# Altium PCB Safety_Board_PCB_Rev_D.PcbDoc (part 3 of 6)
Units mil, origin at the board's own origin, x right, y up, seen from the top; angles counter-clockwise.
Board outline 11000 x 4400 mil, 6 copper layers (L1-TOP, L2-Plane, L3-Signal, L4-Signal, L5-Plane, L6-BOT); 712 components, 540 nets, 2214 pads, 875 vias.
Unrouted connection lines stored in the file: 3.
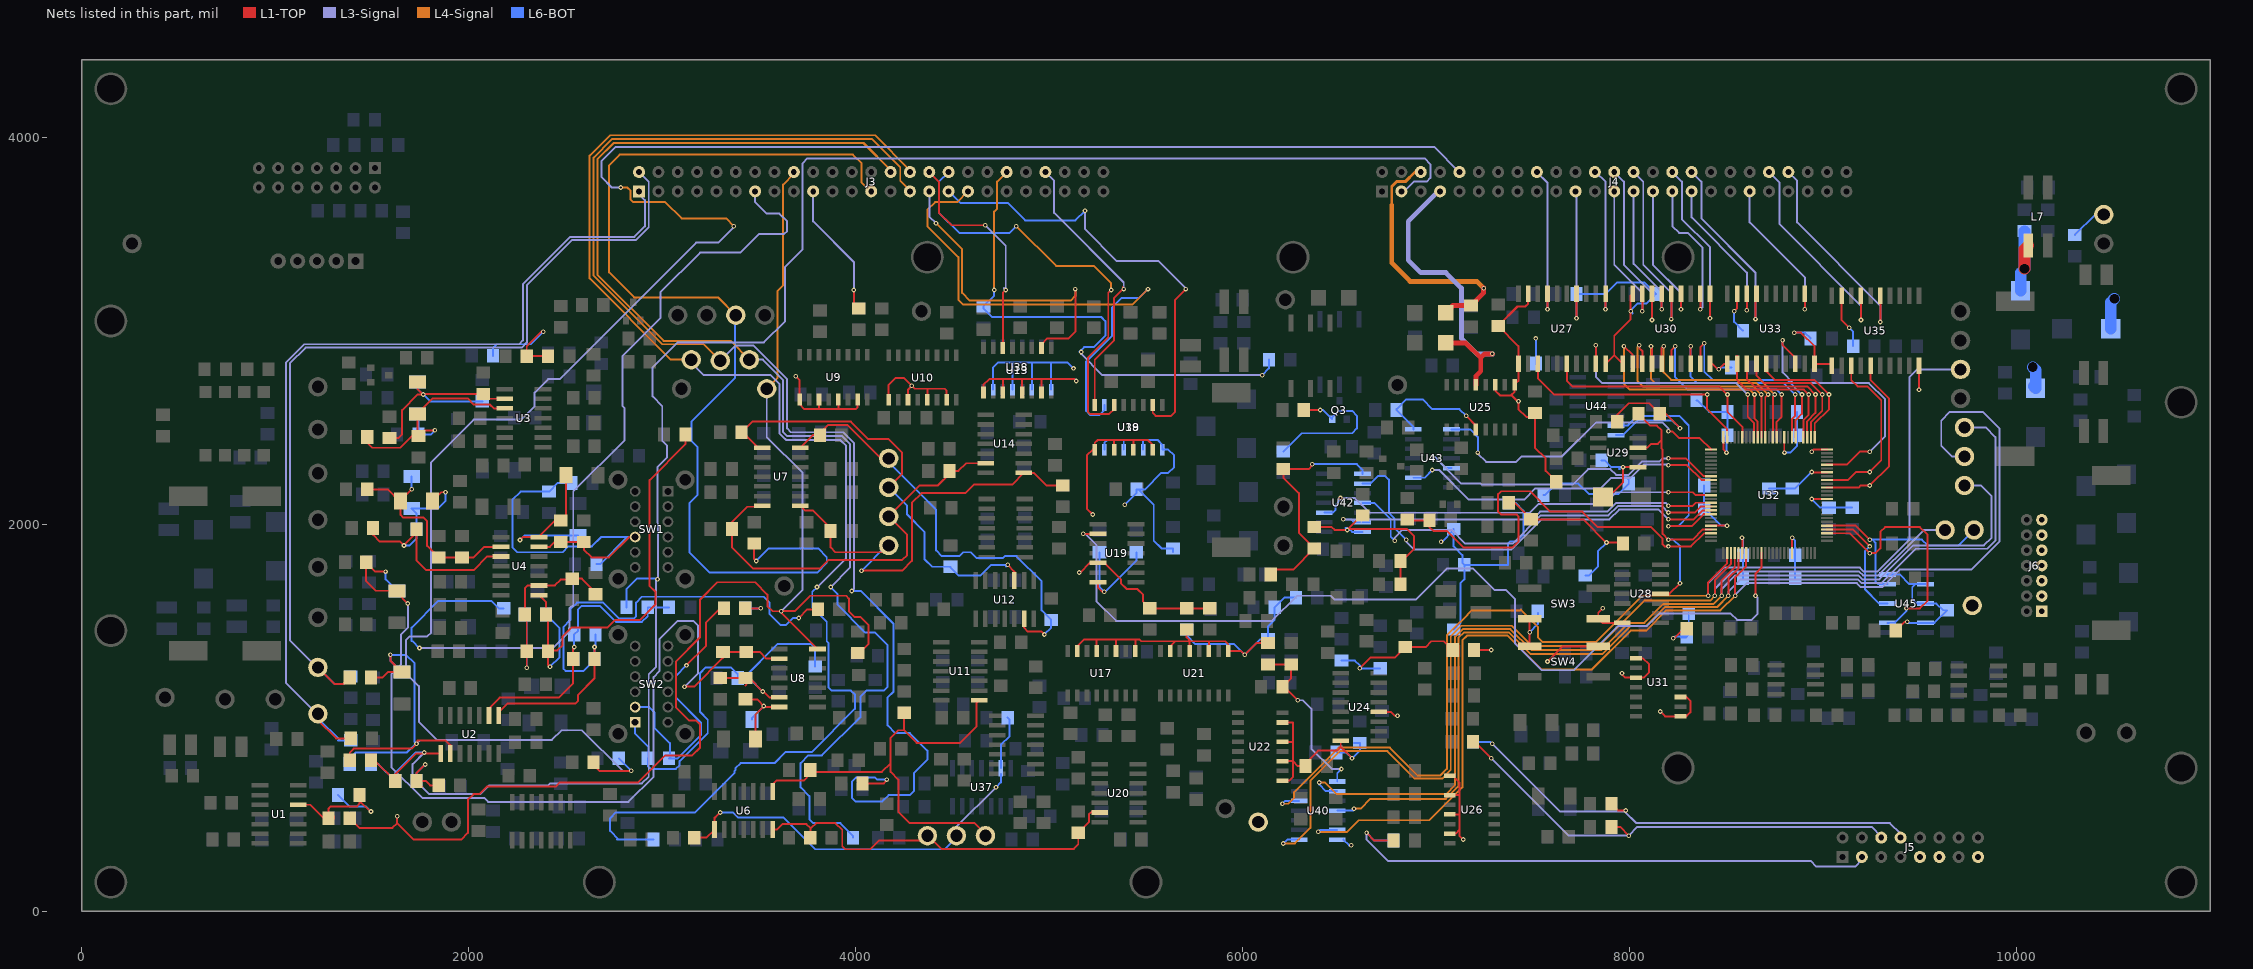
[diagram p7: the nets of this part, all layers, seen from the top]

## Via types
v1: diameter 24, hole 12, L1-TOP to L6-BOT, 720 vias
v2: diameter 50, hole 28, L1-TOP to L6-BOT, 138 vias
v3: diameter 28, hole 50, L1-TOP to L6-BOT, 17 vias

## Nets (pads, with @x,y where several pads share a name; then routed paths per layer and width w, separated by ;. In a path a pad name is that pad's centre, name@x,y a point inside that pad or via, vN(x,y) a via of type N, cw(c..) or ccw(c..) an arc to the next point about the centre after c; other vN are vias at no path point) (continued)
DEC_OVERSPEED_N: TP47.1 U32.55 U45.6 | length 1125.4
  L1-TOP w10: U32.55@9019.21,1992.52 9167.48,1992.52 v1(9240,1920)
  L6-BOT w10: v1(9240,1920) 9510,1920 9540,1890 9700,1890 TP47.1@9780,1970 ; 9255,1920 9270,1905 9270,1705 9285,1690 U45.6@9331.57,1690
DEC_STOP_N_LATCH: U32.77 U33.4 | length 685.3
  L1-TOP w10: U33.4@8655,2828.9 8655,2770 8696,2729 8936,2729 v1(8995,2670) 8995,2585 8936.54,2526.54 U32.77@8936.54,2449.21
DEC_STOP_NORTH_BUF_N: U32.9 U43.2 | length 1727
  L1-TOP w10: v1(8200,2305) 8295,2305 8371.26,2228.74 U32.9@8420.79,2228.74
  L3-Signal w10: v1(6980,2280) 7015,2280 7168,2127 7454.67,2127 7512.67,2185 7850,2185 7903,2238 8003,2238 8073,2308 8197,2308 v1(8200,2305)
  L6-BOT w10: U43.2@6881.57,2240 6940,2240 v1(6980,2280)
DEC_STOP_S_LATCH: U32.76 U33.5 | length 665
  L1-TOP w10: U33.5@8705,2828.9 8705,2790 8749,2746 8954,2746 v1(9030,2670) 9030,2595 8956.22,2521.22 U32.76@8956.22,2449.21
DEC_STOP_SOUTH_BUF_N: U32.16 U42.4 | length 2102.8
  L1-TOP w10: v1(8200,2060) 8335,2060 8365.94,2090.94 U32.16@8420.79,2090.94
  L3-Signal w10: v1(6785,1915) 6785,1930 6825,1970 7080,1970 7150,1900 7395.96,1900 7540.96,2045 7890,2045 7938,2093 8167,2093 v1(8200,2060)
  L6-BOT w10: U42.4@6618.43,2110 6680,2110 6765,2025 6765,1935 v1(6785,1915)
DGND: C25.1 C26.1 C27.1 C28.1 C29.1 C30.1 C31.1 C32.1 C33.1 C34.1 C35.1 C36.1 C37.1 C38.2 C39.1 C40.1 C42.1 C104.1 C105.1 C106.1 C108.1 C109.1 C114.1 C115.1 C116.1 C117.1 C118.1 C119.1 C120.1 C121.1 C122.1 C123.1 C124.1 C125.1 C126.1 C127.1 C128.1 C129.1 C130.1 C131.1 C132.1 C133.1 C134.1 C135.1 C136.1 C137.1 C138.1 C139.1 C140.1 C141.1 C142.1 C143.1 C144.1 C145.1 C146.1 C147.1 C148.1 C149.1 C150.1 C151.1 C152.1 C154.1 C155.1 C156.1 C157.2 C159.2 C161.2 J5.15 J6.1 J6.3 J6.5 J6.7 J6.9 J6.11 J6.13 L7.3 Q3.2 R128.2 R153.1 R161.1 R169.1 R374.1 R383.2 R387.1 SW3.1 SW3.3 SW4.1 SW4.3 TP34.1 TP48.1 TP50.1 U9.9 U9.11 U9.13 U9.15 U10.9 U10.11 U10.13 U10.15 U13.9 U13.11 U13.13 U13.15 U17.9 U17.11 U17.13 U17.15 U18.9 U18.11 U18.13 U18.15 U19.7 U21.9 U21.11 U21.13 U21.15 U22.9 U22.11 U22.13 U22.15 U24.8 U24.12 U25.4 U25.9 U25.11 U26.9 U26.11 U26.13 U26.15 U27.1 U27.10 U27.19 U28.7 U29.1 U30.1 U30.10 U30.19 U31.2 U31.4 U31.9 U31.11 U32.21 U32.31 U32.44 U32.62 U32.69 U32.75 U32.84 U32.100 U33.1 U33.10 U33.19 U35.1 U35.10 U35.19 U38.9 U38.11 U38.13 U38.15 U39.9 U39.11 U39.13 U39.15 U40.7 U42.7 U43.7 U44.7 U45.7 U45.9 U45.11 U45.13 | length 27059.8
  L1-TOP w10: v1(3690,2765) 3710,2745 3710,2620 3735,2595 4000,2595 4010,2605 U9.15@4010,2644.84 ; 3810,2595 U9.11@3810,2644.84 ; 3910,2595 U9.13@3910,2644.84 ; U10.9@4170,2642.84 4170,2720 4205,2755 4250,2755 4305,2700 4460,2700 4470,2690 U10.15@4470,2642.84 ; U10.11@4270,2642.84 4270,2695 v1(4290,2715) ; U10.13@4370,2642.84 4370,2700 ; U13.9@4660,2679.84 4660,2720 4690,2750 5130,2750 v1(5140,2740) ; U13.11@4760,2679.84 4760,2750 ; U13.13@4860,2679.84 4860,2750 ; U13.15@4960,2679.84 4960,2750 ; U17.15@5145,1345.16 5145,1370 5180,1405 5465,1405 5475,1395 5910,1395 5925,1380 U21.9@5925,1345.16 5989.84,1345.16 v1(6010,1325) 6070.12,1385.12 C26.1@6130,1385.12 ; v1(5225,2050) 5195,2080 5195,2355 5224.84,2384.84 U18.9@5235,2384.84 5235,2420 5250,2435 5510,2435 5535,2410 U18.15@5535,2384.84 ; U17.13@5245,1345.16 5245,1405 ; U19.7@5251.57,1700 5251.57,1673.43 5275,1650 v1(5285,1650) ; U18.11@5335,2384.84 5335,2435 ; U17.11@5345,1345.16 5345,1405 ; U18.13@5435,2384.84 5435,2435 ; 5440,1405 5445,1400 U17.9@5445,1345.16 ; U21.15@5625,1345.16 5625,1370 5650,1395 ; C25.1@5710,1454.88 5710,1415 5730,1395 ; U21.13@5725,1345.16 5725,1395 ; U21.11@5825,1345.16 5825,1395 ; C26.1@6095.12,1400.12 C26.1@6135,1400.12 ; U22.9@6205.16,675 6240,675 6260,695 6260,975 U22.15@6205.16,975 ; U22.11@6205.16,775 6260,775 6285,750 C28.1@6324.88,750 6324.88,764.88 6390,830 6488.15,830 6506.57,848.43 ; U22.13@6205.16,875 6260,875 ; R128.2@6305,2600.12 R128.2@6315.12,2590 v1(6400,2590) ; C27.1@6370,1985.12 6459.88,1985.12 6475,1970 v1(6540,1970) 6614.88,2044.88 C29.1@6620,2044.88 ; U24.8@6506.57,880 6506.57,848.43 ; v1@6545,1975 6850,1975 6885,1940 6885,1870 6825,1810 C30.1@6815.12,1810 C31.1@6815.12,1690 ; v1(6565,790) 6506.57,848.43 ; v1(6605,1255) 6660,1310 6785.12,1310 C32.1@6840,1364.88 6944.88,1364.88 6975,1395 7039.88,1395 R153.1@7084.88,1350 ; U24.12@6703.43,1030 6765,1030 6785,1010 v1(6800,1010) ; v1(7025,1910) v1@7030,1915 ; U26.15@7069.84,400 7100,400 7120,420 ; U26.13@7069.84,500 7120,500 ; U26.11@7069.84,600 7120,600 ; U26.9@7069.84,700 7085,700 7120,665 7120,390 v1(7140,370) ; v1(7155,2560) 7205,2510 U25.4@7205,2489.84 ; U25.11@7305,2720.16 7305,2690 7330,2665 7390,2665 7420,2635 v1(7425,2635) 7425,2595 7465.12,2554.88 R161.1@7510,2554.88 ; C33.1@7320,3024.88 7425,2919.88 7425,2740.16 U25.9@7405,2720.16 7405,2685 7385,2665 ; C33.1@7320,3025 7420,3125 7460,3125 7475,3140 U27.19@7475,3191.1 ; C34.1@7375.12,2110 7405.12,2110 C35.1@7490,2025.12 7759.88,2025.12 v1@7885,1900 ; SW4.1@7482.83,1368.74 SW3.3@7482.83,1511.26 ; R161.1@7510,2574.88 7510,2395 7565,2340 7565,2274.88 C36.1@7619.88,2220 ; v1(7575,1290) 7653.74,1368.74 SW4.3@7837.17,1368.74 ; v1(7860,1565) 7837.17,1542.16 SW3.1@7837.17,1511.26 7858.43,1490 U28.7@7961.57,1490 ; C38.2@7861.57,2140 7890,2140 7964.96,2214.96 v1(7964.96,2295.04) U29.1@8042.32,2295.04 ; U27.10@7876.1,2828.9 U27.10@7875,2828.9 7920,2873.9 ; v1(7880,1905) 7959.88,1905 C39.1@7964.88,1900 ; C37.1@7935.12,2530 7935.12,2565.12 7995,2625 8100.12,2625 R169.1@8155.12,2570 8185,2570 v1(8260,2495) ; v1(7960,1230) 7960,1225 7978.08,1206.92 8071.92,1206.92 8100,1235 8100,1275 8068.08,1306.92 U31.2@8032.81,1306.92 ; U30.1@7963.9,2828.9 U30.1@7965,2828.9 7920,2873.9 ; U30.19@8015,3191.1 8005,3181.1 8005,3060 7920,2975 7920,2873.9 ; v1(8157.96,1031.92) 8182.96,1006.92 8292.96,1006.92 8312.96,1026.92 8312.96,1086.92 8292.96,1106.92 U31.11@8263.12,1106.92 ; v1(8225,1410) 8230,1410 8280,1460 C40.1@8294.88,1460 ; U30.10@8415,2828.9 8426.1,2828.9 8455,2800 v1(8460,2800) 8488.9,2828.9 U33.1@8505,2828.9 ; U32.21@8420.79,1992.52 v1(8502.48,1992.52) ; U32.100@8483.78,2449.21 8483.78,2386.22 v1(8500,2370) ; v1(8540,3100) 8555,3115 U33.19@8555,3191.1 ; v1(8580,1930) 8582.2,1927.8 U32.31@8582.2,1850.79 ; U32.84@8798.74,2449.21 8798.74,2366.26 8800,2365 v1(8800,2370) ; U32.44@8838.11,1850.79 8838.11,1933.11 8840,1935 v1(8840,1930) ; v1(8850,2990) 8885,2990 8955,2920 U33.10@8955,2828.9 9035,2828.9 U35.1@9045,2818.9 ; v1(8940,2130) 8940.32,2130.32 U32.62@9019.21,2130.32 ; v1(8940,2270) 8941.89,2268.11 U32.69@9019.21,2268.11 ; v1(8940,2375) 8951.22,2386.22 U32.75@9019.21,2386.22 ; U35.19@9095,3181.1 9095,3055 v1(9135,3015) ; C42.1@9375.12,1450 9420.12,1495 v1(9435,1495) ; v1(9495,2695) U35.10@9495,2818.9
  L1-TOP w60: v3(10040,3320) 10040,3420 L7.3@10060,3440
  L6-BOT w10: U38.15@4710,2694.84 4710,2810 4735,2835 5095,2835 v1(5125,2805) ; U38.13@4810,2694.84 4810,2835 ; U38.11@4910,2694.84 4910,2835 ; U38.9@5010,2694.84 5010,2835 ; C105.1@5260,1854.88 5260,1675 v1(5285,1650) ; U39.15@5285,2384.84 5285,2420 5300,2435 5560,2435 5585,2410 U39.9@5585,2384.84 5615.16,2384.84 5645,2355 5645,2295 5615,2265 5580,2265 5495,2180 C104.1@5450.24,2180 5450.24,2160.24 v1(5390,2100) ; v1@5288.34,1650 5450,1811.66 C106.1@5450,1854.88 ; U39.13@5385,2384.84 5385,2435 ; C104.1@5460,2180 5540,2100 5540,1915 5580.12,1874.88 C108.1@5640,1874.88 C108.1@5640,1855 ; U39.11@5485,2384.84 5485,2435 ; C109.1@5710,1454.88 5710,1425 5755,1380 5955,1380 v1(6010,1325) 6090.12,1405.12 C115.1@6130,1405.12 6130,1470 6165.12,1505.12 C114.1@6165.12,1570 6215.12,1620 C117.1@6274.88,1620 ; C116.1@6210,2375.12 6304.88,2470 6565,2470 6590,2495 6590,2560 6565,2585 6495,2585 6462.6,2552.6 Q3.2@6462.6,2542.76 6415.35,2590 v1(6400,2590) ; C118.1@6485.12,820 6535,820 v1(6565,790) 6605,830 C120.1@6605,869.88 C120.1@6574.88,869.88 ; C119.1@6510,1295.12 6579.88,1295.12 6605,1270 v1(6605,1255) 6709.88,1255 C122.1@6710,1255.12 ; U40.7@6520,370 6550,340 v1(6560,340) ; 6530,1980 v1@6540,1980 ; v1(6540,1970) 6555,1970 6565,1960 U42.7@6618.43,1960 ; U43.7@6881.57,2490 6881.57,2503.54 C121.1@6795.12,2590 6795.12,2595.12 6845,2645 6930,2645 6980,2595 7120,2595 v1(7155,2560) ; v1(7025,1910) 7025,1905 C123.1@7090,1970 ; C125.1@7090,1455.12 7125,1490.12 7125,1695 7145.12,1715.12 C124.1@7145.12,1790 ; C123.1@7090,1974.88 7090,1885 7135.12,1839.88 7135.12,1800 C124.1@7145.12,1790 ; C126.1@7375.12,2110 7410,2110 7450,2070 7450,1945 7415,1910 7380,1910 7370,1900 7370,1790 C124.1@7145.12,1790 ; v1(7482.83,1442.16) 7525.12,1484.45 C127.1@7525.12,1540 ; C128.1@7514.88,2830 7514.88,2959.88 v1(7515,2960) ; C130.1@7554.88,2150 7560,2150 7620,2210 7735,2210 7790,2155 7939.88,2155 C133.1@7994.88,2210 7994.88,2230.12 7964.96,2260.04 v1(7964.96,2295.04) 7904.96,2295.04 7870,2330 C132.1@7855.12,2330 ; C129.1@7725.12,3190 7875,3190 7935,3250 8075.12,3250 C134.1@8135.12,3190 8085.12,3140 8040,3140 8005,3105 v1(8005,3100) ; C131.1@7770,1735.12 7790.12,1735.12 7835,1780 7835,1860 v1(7880,1905) ; U44.7@7928.43,2460 7965,2460 8040,2535 8220,2535 v1(8260,2495) ; 7945,2285 7950,2285 ; v1@8000,3100 v1(8005,3100) ; 8015.12,3089.88 v1(8005,3100) ; v1(8225,1410) 8235,1420 C141.1@8294.88,1420 ; C141.1@8265,1415 8289.88,1415 8305.12,1430.24 C136.1@8305.12,1540 ; C135.1@8345.12,2640 8350,2640 8410,2580 C145.1@8504.88,2580 C137.1@8504.88,2460 8500,2455.12 v1(8500,2370) ; C142.1@8384.88,2200 C138.1@8384.88,2080 8472.36,1992.52 v1(8502.48,1992.52) ; v1(8460,2800) 8470,2810 C144.1@8524.88,2810 ; v1(8540,3100) 8540,3045.12 C143.1@8585.12,3000 ; v1(8580,1930) 8585.12,1924.88 C140.1@8585.12,1720 ; C146.1@8720,2185.12 C149.1@8840,2185.12 8855.12,2185.12 v1(8940,2270) ; v1(8800,2370) 8830,2370 8865.12,2405.12 C147.1@8865.12,2580 ; v1(8840,1930) 8855.12,1914.88 C151.1@8855.12,1720 ; v1(8850,2990) 8904.88,2990 C152.1@8934.88,2960 ; v1(8940,2130) 8984.88,2085.12 C155.1@9150,2085.12 ; v1(9135,3015) 9154.88,2995.12 R374.1@9154.88,2920 ; U45.7@9331.57,1740 9395,1740 9445,1690 U45.9@9528.43,1690 ; v1(9435,1495) 9440,1490 9574.88,1490 C156.1@9640,1555.12 9619.88,1555.12 9585,1590 9485,1590 9460,1615 9460,1675 9475,1690 ; R387.1@10300,3495.12 10300.12,3495.12 10405,3600 TP50.1@10450,3600
  L6-BOT w60: C157.2@10020,3205.98 10020,3300 ; v3(10040,3320) R383.2@10040,3514.88 ; v3(10082.96,2811.92) 10097.96,2796.92 C159.2@10097.96,2702.9 C159.2@10087.96,2712.9 ; C161.2@10485.98,3010 10485.98,3145.98 v3(10505,3165)
"DOME1 CURRENT": J3.28 R252.1 TP22.1 | length 6741.3
  L4-Signal w10: TP22.1@3450,2850 3353,2947 3007.04,2947 2665,3289.04 2665,3885 2750,3970 4040,3970 4180,3830 J3.28@4180,3820
  L3-Signal w10: TP22.1@3450,2850 3520,2850 3625,2745 3625,2475 3645,2455 3930,2455 3970,2415 3970,1775 v1(3870,1675)
  L6-BOT w10: v1(3870,1675) 3905,1640 3905,1585 4050,1440 4100,1440 4165,1375 4165,1160 4145,1140 4055,1140 4025,1110 4025,1005 3824.62,804.62 3754.62,804.62 3715,765 3715,640 3760,595 3760,475 3780,455 3920,455 3985.12,389.88 R252.1@3985.12,380
"DOME1 OC LATCH": J4.24 U27.11 | length 816.8
  L1-TOP w10: v1(7875,3110) U27.11@7875,3191.1
  L3-Signal w10: J4.24@7820,3820 7825,3820 7875,3770 v1(7875,3110)
DOME1_OVERCURRENT_LATCH: U27.9 U32.92 | length 1315.9
  L1-TOP w10: U27.9@7825,2828.9 v1(7825,2925) ; v1(8610,2670) 8610,2555 8641.26,2523.74 U32.92@8641.26,2449.21
  L3-Signal w10: v1(7825,2925) 7825,2762 7858,2729 8551,2729 v1(8610,2670)
DOME1_OVERCURRENT_N: TP44.1 U32.30 U40.4 | length 5510
  L1-TOP w10: v1(8510,1630) 8510,1720 8562.52,1772.52 U32.30@8562.52,1850.79
  L4-Signal w10: v1(6575,530) 6610,530 6660,580 7049.92,580 7115,645.08 7115,1411.92 7144.08,1441 7375.92,1441 7486.92,1330 7860,1330 8003,1473 8083,1473 8181,1571 8451,1571 v1(8510,1630)
  L3-Signal w10: v1(8510,1630) 8510,1650 8575,1715 9177.88,1715 9197.88,1695 9300,1695 9478,1873 9848,1873 9890,1915 9890,2450 9840,2500 TP44.1@9730,2500
  L6-BOT w10: U40.4@6488.43,520 6570,520 6575,525 v1(6575,530)
"DOME2 CURRENT": J3.29 R76.1 TP19.1 | length 7217.2
  L1-TOP w10: R76.1@4035.12,660 4145,660 4165,680 v1(4160,680)
  L4-Signal w10: TP19.1@3300,2845 3215,2930 3000,2930 2645,3285 2645,3895 2740,3990 4085,3990 4230,3845 4230,3775 4280,3725 J3.29@4280,3720
  L3-Signal w10: TP19.1@3300,2845 3378,2923 3472,2923 3645,2750 3645,2495 3665,2475 3935,2475 3990,2420 3990,1665 v1(3980,1655)
  L6-BOT w10: v1(3980,1655) 4025,1655 4195,1485 4195,1135 4165,1105 4165,960 4205,920 4280,920 4370,830 4370,783.34 4300,713.34 4300,620 4280,600 4170,600 4137,567 3998,567 3980,585 3980,670 4000,690 4100,690 4110,680 v1(4160,680)
"DOME2 OC LATCH": J4.25 U30.18 | length 771.2
  L1-TOP w10: v1(8065,3100) U30.18@8065,3191.1
  L3-Signal w10: J4.25@7920,3720 7920,3340 8065,3195 v1(8065,3100)
DOME2_OVERCURRENT_LATCH: U30.2 U32.91 | length 1229.9
  L1-TOP w10: v1(7970,2920) 8015,2875 U30.2@8015,2828.9 ; v1(8645,2670) 8645,2545 8660.94,2529.06 U32.91@8660.94,2449.21
  L4-Signal w10: v1(7970,2920) 7970,2725 8000,2695 8620,2695 v1(8645,2670)
DOME2_OVERCURRENT_N: TP45.1 U32.32 U40.6 | length 6308.7
  L1-TOP w10: v1(8545,1630) 8545,1725 8601.89,1781.89 U32.32@8601.89,1850.79
  L4-Signal w10: v1(6390,410) 6540,410 6600,470 6963.96,470 7113,619.04 7114.04,619.04 7135,640 7135,1400 7159,1424 7368.88,1424 7542.88,1250 7805,1250 8005,1450 8085,1450 8189,1554 8469,1554 v1(8545,1630)
  L3-Signal w10: v1(8545,1630) 8545,1635 8605,1695 9173.83,1695 9193.83,1675 9305,1675 9395,1765 9765,1765 9910,1910 9910,2495 9825,2580 9655,2580 9610,2535 9610,2405 9665,2350 TP45.1@9730,2350
  L6-BOT w10: v1(6390,410) 6400,420 U40.6@6488.43,420
"DOME3 CURRENT": J3.30 R239.1 TP18.1 | length 7701
  L4-Signal w10: TP18.1@3150,2850 3045,2850 2625,3270 2625,3905 2730,4010 4100,4010 4280,3830 J3.30@4280,3820
  L3-Signal w10: TP18.1@3180,2850 TP18.1@3150,2850 3150,2835 3215,2770 3560,2770 3605,2725 3605,2470 3635,2440 3635.96,2440 3640.96,2435 3920,2435 3950,2405 3950,1825 v1(3800,1675)
  L6-BOT w10: 2765,370 R239.1@2954.88,370 ; 2775,370 2730,415 2730,480 2760,510 3170,510 3373.13,713.13 3373.13,723.53 3377.77,728.16 3377.77,737.77 3405,765 3580,765 3636.62,821.62 3771.62,821.62 3995,1045 3995,1120 3975,1140 3875,1140 3860,1155 3860,1385 3850,1395 3850,1495 3775,1570 3775,1650 v1(3800,1675)
"DOME3 OC LATCH": J4.26 U30.17 | length 981.9
  L1-TOP w10: v1(8115,3055) U30.17@8115,3191.1
  L3-Signal w10: J4.26@7920,3820 7970,3770 7970,3340 8115,3195 v1(8115,3055)
DOME3_OVERCURRENT_LATCH: U30.3 U32.90 | length 1181.5
  L1-TOP w10: v1(8050,2925) 8050,2910 8065,2895 U30.3@8065,2828.9 ; v1(8680,2670) 8680.63,2669.37 U32.90@8680.63,2449.21
  L4-Signal w10: v1(8050,2925) 8040,2915 8040,2740 8068,2712 8638,2712 v1(8680,2670)
DOME3_OVERCURRENT_N: TP46.1 U32.29 U40.2 | length 5369
  L1-TOP w10: v1(8475,1630) 8475,1710 8542.83,1777.83 U32.29@8542.83,1850.79
  L4-Signal w10: v1(6395,665) 6425,665 6485,605 7050.88,605 7098,652.12 7098,1418.96 7137.04,1458 7382.96,1458 7490.96,1350 7855,1350 7995,1490 8075.96,1490 8173.96,1588 8433,1588 v1(8475,1630)
  L3-Signal w10: v1(8475,1630) 8475,1665 8545,1735 9181.92,1735 9201.92,1715 9290,1715 9465,1890 9830,1890 9870,1930 9870,2145 9815,2200 TP46.1@9730,2200
  L6-BOT w10: v1(6395,665) 6395,655 6430,620 U40.2@6488.43,620
"DOME AMP": D12.K J4.6 R151.1 | length 1366.9
  L1-TOP w25: D12.K@7050,3093.5 7086.62,3130.12 R151.1@7180,3130.12 7245,3195.12 v1(7245,3220)
  L4-Signal w15: 6770,3650 6770,3745 6795,3770 6840,3770 6890,3820 J4.6@6920,3820
  L4-Signal w25: 6770,3650 6770,3350 6865,3255 7210,3255 v1(7245,3220)
"DOME AMP ENABLE & THERM STAT LATCH": J4.42 U35.17 | length 1087.9
  L1-TOP w10: v1(9195,3055) U35.17@9195,3181.1
  L3-Signal w10: J4.42@8720,3820 8775,3765 8775,3550 9195,3130 v1(9195,3055)
"DOME AMP RET": D12.A J4.7 U25.13 | length 1647.6
  L1-TOP w25: D12.A@7050,2936.5 7153.5,2936.5 7230,2860 ; U25.13@7205,2720.16 7205,2765 7230,2790 7230,2860 ; v1(7290,2880) 7250,2880 7230,2860
  L3-Signal w25: J4.7@7020,3720 7010,3720 6855,3565 6855,3365 6920,3300 7050,3300 7130,3220 7130,2960 7210,2880 v1(7290,2880)
DOME_AMP_ENABLE_&_THERM_STAT: U32.8 U43.12 | length 1738.7
  L1-TOP w10: v1(8200,2340) 8290,2340 8381.57,2248.43 U32.8@8420.79,2248.43
  L3-Signal w10: v1(6980,2345) 6995,2345 7130,2210 7230,2210 7235,2205 7705,2205 7785,2285 7900,2285 7930,2255 7995,2255 8065,2325 8155,2325 8170,2340 v1(8200,2340)
  L6-BOT w10: v1(6980,2345) 6995,2345 7050,2290 U43.12@7078.43,2290
DOME_AMP_ENABLE_&_THERM_STAT_LATCH: U32.67 U35.3 | length 905.1
  L1-TOP w10: U32.67@9019.21,2228.74 9128.74,2228.74 9170,2270 v1(9240,2270) 9300,2330 9300,2640 9228,2712 9178,2712 9145,2745 U35.3@9145,2818.9
DOME_AMP_ENABLE_N: R146.1 R150.2 U32.23 | length 2274.1
  L1-TOP w10: R146.1@6850,2024.88 6854.88,2020 R150.2@6964.88,2020 6964.88,1985.12 6985,1965 7055,1965 7140,1880 7395,1880 7425,1910 7425,2040 7415,2050 7335,2050 7320,2065 7320,2155 7335,2170 7485,2170 7590,2065 7755,2065 7835,1985 8110,1985 8170,1925 8170,1895 8180,1885 8315.96,1885 8384.11,1953.15 U32.23@8420.79,1953.15
  other v1: 8200,1885
"EAST CURRENT": J3.25 R58.1 TP20.1 | length 5424
  L1-TOP w10: R58.1@3475,1899.88 3475,1820 v1(3485,1810)
  L4-Signal w10: TP20.1@3380,3080 3288,3172 2854.17,3172 2725,3301.17 2725,3855 2780,3910 3985,3910 4030,3865 4030,3765 4075,3720 J3.25@4080,3720
  L6-BOT w10: 3375,3030 3375,2755 3150,2530 3150,2430 3183,2397 3183,2152.04 3140,2109.04 3140,1855 3245,1750 3800,1750 3850,1800 3850,1830 3805,1875 3550,1875 v1(3485,1810)
"EAST DRIVE+": C57.2 J3.1 R16.1 TP12.1 | length 4886.7
  L1-TOP w10: TP12.1@1220,1020 1220,987.76 1314.65,893.11 R16.1@1389.53,893.11
  L3-Signal w10: TP12.1@1220,1020 1215,1020 1055,1180 1055,2835 1150,2930 2260,2930 2280,2950 2280,3240 2525,3485 2855.96,3485 2910,3539.04 2910,3675 2880,3705 J3.1@2880,3720
  L6-BOT w10: TP12.1@1220,1020 1220,997.99 1335,882.99 ; 1324.76,882.99 C57.2@1389.65,882.99
"EAST DRIVE-": C54.2 J3.2 R15.1 TP11.1 | length 4693.8
  L1-TOP w10: TP11.1@1220,1260 1305,1175 1351.42,1175 R15.1@1384.53,1208.11
  L3-Signal w10: TP11.1@1220,1260 1215,1260 1075,1400 1075,2830.96 1157.04,2913 2273,2913 2300,2940 2300,3235.96 2532.04,3468 2863,3468 2930,3535 2930,3770 J3.2@2880,3820
  L6-BOT w10: TP11.1@1220,1260 1305,1175 1351.42,1175 C54.2@1389.65,1213.23
"EAST OC LATCH": J4.21 U27.14 | length 783.2
  L1-TOP w10: v1(7725,3065) U27.14@7725,3191.1
  L3-Signal w10: J4.21@7720,3720 7725,3715 v1(7725,3065)
"EAST TACH OUT": C4.1 C8.1 J4.3 R207.1 R212.1 R236.1 U2.1 | length 9949.5
  L1-TOP w10: C4.1@1495.12,780 1512.64,780 C8.1@1619.53,673.11 1619.53,707.99 1726.22,814.69 1764.69,814.69 v1(1770,820) 1775.31,814.69 U2.1@1854.65,814.69
  L3-Signal w10: v1(1770,820) 1710,760 1710,690 1795,605 2060,605 2105,650 2410.7,650 2420.7,660 2895,660 2930,695 2930,1225 2968,1263 v1@2968,1708 ; v1@2976.98,1715.01 2975,2295 3025,2345 3025,2405 3000,2430 3000,2610 2950,2660 2950,2810 3080,2940 3525,2940 3635,3050 3635,3330 3725,3420 3725,3865 3750,3890 6940,3890 6970,3860 6970,3790 6950,3770 6885,3770 6835,3720 J4.3@6820,3720
  L6-BOT w10: R207.1@1495.12,760 1532.64,760 R212.1@1619.53,673.11 1619.53,714.53 1725,820 v1(1770,820) ; R236.1@2814.88,1570 2814.88,1664.88 2870,1720 2980,1720 v1(2975,1715)
"EAST VEL IN": J3.13 R220.2 | length 4542
  L3-Signal w10: v1(1745,1360) 2435,1360 2520,1445 2520,1565 2530,1575 2540,1575 2540,2169.04 2805,2434.04 2805,2600 2795,2610 2795,2870 2990,3065 2990,3197.88 3195.12,3403 3403,3403 3500,3500 3630,3500 3645,3515 3645,3565 3605,3605 3540,3605 3480,3665 J3.13@3480,3720
  L6-BOT w10: v1(1745,1360) 1710,1395 1705,1395 1705,1465 1843,1603 2117,1603 2154.88,1565.12 R220.2@2180,1565.12
"EAST VEL OUT": C77.2 J4.10 R43.2 | length 10566
  L1-TOP w10: R43.2@2645.12,770 2645.12,754.88 2675,725 v1(2840,725)
  L4-Signal w10: v1(2785,3740) 2820,3740 2835,3725 2835,3680 2850,3665 3015,3665 3100,3580 3330,3580 v1(3370,3540)
  L3-Signal w10: v1(2785,3740) 2740,3740 2685,3795 2685,3875 2760,3950 6990,3950 J4.10@7120,3820 ; v1(2840,725) 2795,725 2585,935 2480,935 2430,885 1835,885 1742.27,977.73 1742.27,1162.73 1675,1230 1675,1400 1695,1420 1785,1420 1805,1440 1805,2320 2025,2540 2270,2540 2340,2610 2340,2680 2410,2750 2470,2750 3175,3455 3290,3455 3370,3535 v1(3370,3540)
  L6-BOT w10: C77.2@2775.12,790 2775.12,789.88 v1(2840,725)
EAST_ENCODER_BUF: J5.3 R141.1 R321.2 | length 2995.4
  L1-TOP w10: v1(6640,405) 6680,365 R141.1@6779.88,365
  L3-Signal w10: v1(6640,405) 6640,370 6750,260 8935,260 8965,230 9165,230 9200,265 J5.3@9200,280
  L6-BOT w10: v1(6640,405) 6680,365 R321.2@6779.88,365
EAST_ENCODER_IN: J5.6 R149.1 R168.1 | length 2463.6
  L1-TOP w10: R149.1@7190.12,875 7200,875 v1(7285,790) ; R168.1@7905.12,435 7950,435 v1(7995,390)
  L3-Signal w10: v1(7285,790) 7685,390 v1(7995,390) 8040,435 9250,435 9300,385 J5.6@9300,380
EAST_ENCODER_RTN: J5.8 R167.1 R332.1 | length 2516
  L1-TOP w10: R167.1@7905.12,555 7940.12,520 v1(7980,520)
  L3-Signal w10: v1(7290,865) 7640,515 7975,515 8035,455 9345,455 9400,400 J5.8@9400,380
  L6-BOT w10: R332.1@7190.12,875 7280,875 v1(7290,865)
EAST_OVERCURRENT_LATCH: U27.6 U32.95 | length 1200.7
  L1-TOP w10: U27.6@7675,2828.9 7675,2740 7703,2712 8463,2712 v1(8505,2670) 8505,2580 8582.2,2502.8 U32.95@8582.2,2449.21
EAST_OVERCURRENT_N: TP42.1 U32.27 U40.12 | length 6042.5
  L1-TOP w10: v1(8405,1630) 8405,1700 8503.46,1798.46 U32.27@8503.46,1850.79
  L4-Signal w10: v1(6205,555) 6235,555 6265,585 6265,615 6495,845 6760,845 6903,702 7022,702 7055,735 7055,1425 7125,1495 7125.96,1495 7160.96,1530 7160.96,1530.96 7184,1554 7433,1554 ; 7437,1558 7525,1470 7525,1415 7550,1390 7825,1390 8065,1630 v1(8405,1630)
  L3-Signal w10: v1(8405,1630) 8405,1695 8485,1775 9190,1775 9210,1755 9280,1755 9445,1920 9445,2760 9485,2800 TP42.1@9710,2800
  L6-BOT w10: v1(6205,555) 6220,570 U40.12@6291.57,570
EGND: J5.9 J5.11 R153.2 | length 89.9
  L1-TOP w10: R153.2@7195.12,1350 v1(7285,1350)
"EMERG STOP": J3.40 R272.2 R310.2 | length 2751.8
  L4-Signal w10: v1(4715,3210) 4715,3615 4730,3630 4730,3770 J3.40@4780,3820
  L3-Signal w10: v1(5165,2890) 5165,2880 5275,2770 v1(6100,2770)
  L6-BOT w10: v1(4715,3210) 4715,3180.12 R272.2@4660,3125.12 4660,3115 4705,3070 5270,3070 5290,3050 5290,2975 5230,2915 5180,2915 5155,2890 v1(5165,2890) ; v1(6100,2770) 6134.88,2804.88 R310.2@6134.88,2850
"EMERG STOP LATCH": J4.27 U30.16 | length 751.2
  L1-TOP w10: v1(8165,3110) U30.16@8165,3191.1
  L3-Signal w10: J4.27@8020,3720 8020,3345 8165,3200 v1(8165,3110)
EMERG_STOP_BUF_N: U32.18 U44.6 | length 1257.1
  L1-TOP w10: v1(8200,1990) 8320,1990 8381.57,2051.57 U32.18@8420.79,2051.57
  L6-BOT w10: U44.6@7928.43,2510 7990,2510 8040,2560 8255,2560 8305,2510 8305,2045 8250,1990 v1(8200,1990)
EMERG_STOP_LATCH: U30.4 U32.89 | length 1128.2
  L1-TOP w10: v1(8110,2920) 8115,2915 U30.4@8115,2828.9 ; U32.89@8700.32,2449.21 8700.32,2655.31 v1(8715,2670)
  L4-Signal w10: v1(8110,2920) 8110,2750 8131,2729 8656,2729 v1(8715,2670)
"HA EMERG E": J3.35 U39.2 | length 2758.2
  L4-Signal w10: J3.35@4580,3720 4525,3665 4410,3665 4370,3625 4370,3540 4530,3380 4530,3160 4555,3135 5430,3135 v1(5510,3215)
  L6-BOT w10: U39.2@5285,2615.16 5285,2590 5260,2565 5210,2565 5190,2585 5190,2840 5325,2975 5325,3120 5375,3170 5465,3170 v1(5510,3215)
"HA EMERG E LATCH": J4.34 U33.17 | length 1006.7
  L1-TOP w10: v1(8650,3060) U33.17@8650,3170
  L3-Signal w10: J4.34@8320,3820 8370,3770 8370,3580 8650,3300 v1(8650,3060)
"HA EMERG W": J3.34 U18.6 | length 2185.3
  L1-TOP w10: v1(5320,3210) 5305,3195 5305,2965 5200,2860 5200,2580 5210,2570 5310,2570 5335,2595 U18.6@5335,2615.16
  L4-Signal w10: v1(4830,3540) 5035,3335 5230,3335 5320,3245 v1(5320,3210)
  L6-BOT w10: J3.34@4480,3820 4430,3770 4430,3610 4535,3505 4795,3505 v1(4830,3540)
"HA EMERG W LATCH": J4.33 U33.18 | length 819.2
  L1-TOP w10: v1(8605,3105) U33.18@8605,3191.1
  L3-Signal w10: J4.33@8320,3720 8320,3585 8605,3300 v1(8605,3105)
"HA OS LATCH": J4.18 U27.17 | length 813.9
  L1-TOP w10: v1(7575,3110) U27.17@7575,3191.1
  L3-Signal w10: J4.18@7520,3820 7575,3765 v1(7575,3110)
"HA STOP E": J3.33 U18.2 | length 2391.6
  L1-TOP w10: U18.2@5535,2615.16 5535,2575 5550,2560 5630,2560 5650,2580 5650,3160 v1(5705,3215)
  L3-Signal w10: v1(5185,3620) 5185,3525 5350,3360 5565,3360 5705,3220 v1(5705,3215)
  L6-BOT w10: J3.33@4480,3700 J3.33@4480,3730 ; J3.33@4480,3720 4540,3660 4785,3660 4875,3570 5135,3570 v1(5185,3620)
"HA STOP E LATCH": J4.32 U30.11 | length 961.9
  L1-TOP w10: v1(8415,3065) U30.11@8415,3191.1
  L3-Signal w10: J4.32@8220,3820 8270,3770 8270,3575 8415,3430 v1(8415,3065)
"HA STOP W": J3.32 U13.6 | length 1196.3
  L1-TOP w10: J3.32@4380,3820 4430,3770 4430,3610 4495,3545 v1(4670,3545) ; U13.6@4760,2910.16 4760,3195 v1(4775,3210)
  L3-Signal w10: v1(4670,3545) 4775,3440 v1(4775,3210) 4765,3220
"HA STOP W LATCH": J4.31 U30.12 | length 785.8
  L1-TOP w10: v1(8365,3110) U30.12@8365,3191.1
  L3-Signal w10: J4.31@8220,3720 8220,3540 8255,3505 8300,3505 8375,3430 8375,3120 v1(8365,3110)
"HA VEL FEEDBACK": J3.18 R7.1 R75.2 TP23.1 U8.14 | length 7167.6
  L1-TOP w10: R7.1@1385.12,480 1435.12,430 1605,430 1630,455 ; v1(1630,490) 1630,455 ; U8.14@3765,1355 U8.14@3801.85,1355 3615,1541.85 v1(3615,1550) ; R75.2@4010,1334.88 4019.88,1334.88 4065,1380 4065,1480 4025,1520 3995,1520 3965,1550 3965,1615 3950,1630 3765,1630 3685.2,1550.2 3615.2,1550.2 v1(3615,1550) ; 1630,455 1715,370 1960,370 1995,405 1995,575 2025,605 2055,605 2095,645 2450.96,645 2470.96,665 2875,665 3015,805 3155,805 3195,845 3195,965 3175,985 3140,985 3070,1055 3070,1290 3195,1415 3195,1610 3285,1700 3480,1700 3543.64,1636.36 3543.64,1576.36 3570,1550 v1(3615,1550)
  L4-Signal w10: TP23.1@3540,2700 3595,2755 3595,3205 3625,3235 3625,3755 3680,3810 J3.18@3680,3820
  L3-Signal w10: TP23.1@3540,2700 3540,2450 3725,2265 3725,1660 v1(3615,1550)
HA_EMERG_E_LATCH: U32.78 U33.3 | length 705.7
  L1-TOP w10: U33.3@8605,2828.9 8605,2750 8643,2712 8918,2712 v1(8960,2670) 8960,2575 8916.85,2531.85 U32.78@8916.85,2449.21
HA_EMERG_EAST_BUF_N: U32.1 U43.8 | length 1612.1
  L1-TOP w10: v1(8200,2480) 8220,2480 8255,2445 8362.01,2445 U32.1@8420.79,2386.22
  L3-Signal w10: v1(7215,2370) 7215,2365 7258,2322 7412.96,2322 7440.96,2350 7650,2350 7825,2525 8170,2525 8200,2495 v1(8200,2480)
  L6-BOT w10: U43.8@7078.43,2490 7175,2490 7215,2450 v1(7215,2370)
HA_EMERG_W_LATCH: U32.79 U33.2 | length 758.4
  L1-TOP w10: U33.2@8555,2870 8555,2745 8605,2695 8900,2695 v1(8925,2670) 8925,2565 8897.17,2537.17 U32.79@8897.17,2449.21
HA_EMERG_WEST_BUF_N: U32.54 U45.4 | length 635.2
  L1-TOP w10: U32.54@9019.21,1972.83 9152.17,1972.83 v1(9240,1885)
  L6-BOT w10: v1(9240,1885) 9215,1860 9215,1665 9290,1590 U45.4@9331.57,1590
HA_OVERSPEED_LATCH: U27.3 U32.99 | length 1247.7
  L1-TOP w10: U27.3@7525,2828.9 7525,2755 7610,2670 v1(8400,2670) 8400,2595 8503.46,2491.54 U32.99@8503.46,2449.21
HA_OVERSPEED_N: TP39.1 U32.28 U40.8 | length 5224.9
  L1-TOP w10: v1(8440,1630) 8440,1710 8523.15,1793.15 U32.28@8523.15,1850.79
  L4-Signal w10: v1(6210,350) 6270,350 6350,430 6350,675 6502.4,827.4 6747.6,827.4 6890,685 7030,685 7062,717 ; 7062,717.96 7075,730.96 7075,1420 7130,1475 7390,1475 7495,1370 7840,1370 8075,1605 8415,1605 v1(8440,1630)
  L3-Signal w10: v1(8440,1630) 8440,1665 8530,1755 9185.96,1755 9205.96,1735 9285,1735 9450,1900 9450.96,1900 9520.96,1970 TP39.1@9630,1970
  L6-BOT w10: v1(6210,350) 6230,370 U40.8@6291.57,370
HA_STOP_E_LATCH: U30.9 U32.81 | length 1048.8
  L1-TOP w10: U30.9@8365,2828.9 8365,2915 v1(8385,2935) ; U32.81@8857.8,2449.21 8857.8,2537.8 8890,2570 v1(8890,2670)
  L6-BOT w10: v1(8385,2935) 8385,2789 8428,2746 8814,2746 v1(8890,2670)
HA_STOP_EAST_BUF_N: U32.13 U42.10 | length 2132.4
  L1-TOP w10: v1(8200,2165) 8325,2165 8340,2150 U32.13@8420.79,2150
  L3-Signal w10: v1(6505,2135) 6580,2135 6656,2059 7482.83,2059 7528.83,2105 7870,2105 7930,2165 v1(8200,2165)
  L6-BOT w10: U42.10@6421.57,2060 6465,2060 6480,2075 6480,2100 6505,2125 v1(6505,2135)
HA_STOP_W_LATCH: U30.8 U32.82 | length 1055
  L1-TOP w10: U30.8@8315,2828.9 v1(8315,2920) ; U32.82@8838.11,2449.21 8838.11,2543.11 8855,2560 v1(8855,2670)
  L6-BOT w10: v1(8315,2920) 8315,2762 8348,2729 8796,2729 v1(8855,2670)
HA_STOP_WEST_BUF_N: U32.15 U42.6 | length 2076.5
  L1-TOP w10: v1(8200,2095) 8325,2095 8340.63,2110.63 U32.15@8420.79,2110.63
  L3-Signal w10: v1(6520,2025) 7496.92,2025 7536.92,2065 7885,2065 7930,2110 8185,2110 v1(8200,2095)
  L6-BOT w10: v1(6520,2025) 6560,2025 6575,2010 U42.6@6605,2010 ; U42.6@6618.43,2010 U42.6@6655,2010
"HORIZON STOP": J3.31 U13.2 | length 1684.1
  L1-TOP w10: U13.2@4960,2910.16 4960,2930 4990,2960 5100,2960 5135,2995 v1(5135,3215)
  L4-Signal w10: v1(4415,3555) 4550,3420 4550,3195 4590,3155 5110,3155 5135,3180 v1(5135,3215)
  L3-Signal w10: J3.31@4380,3720 4380,3590 v1(4415,3555)
"HORIZON STOP LATCH": J4.39 U33.12 | length 809.2
  L1-TOP w10: v1(8905,3110) U33.12@8905,3191.1
  L3-Signal w10: J4.39@8620,3720 8620,3560 8905,3275 v1(8905,3110)
HORIZON_STOP_BUF_N: U32.17 U42.2 | length 2235.8
  L1-TOP w10: v1(8200,2025) 8330,2025 8376.26,2071.26 U32.17@8420.79,2071.26
  L3-Signal w10: v1(6845,1920) 6845,1910 6885,1870 7390,1870 7545,2025 7895,2025 7945,2075 8150,2075 v1(8200,2025)
  L6-BOT w10: U42.2@6618.43,2210 6660,2210 6700,2250 6735,2250 6755,2230 6755,2059.04 6785,2029.04 6785,1980 v1(6845,1920)
HORIZON_STOP_LATCH: U32.71 U33.8 | length 1452.9
  L1-TOP w10: v1(8790,2950) 8790,2925 8855,2860 U33.8@8855,2828.9 ; U32.71@9019.21,2307.48 9122.48,2307.48 9190,2375 v1(9240,2375)
  L3-Signal w10: v1(8790,2950) 8790,2785 8846,2729 9236,2729 9320,2645 9320,2455 v1(9240,2375)
"HP STOP": J3.44 U18.8 | length 1447.7
  L1-TOP w10: U18.8@5235,2615.16 5235,2850 5335,2950 5335,3170 v1@5380,3215 ; v1@5380,3225 v1@5380,3215 ; v1(5385,3215) v1@5380,3215
  L3-Signal w10: J3.44@4980,3820 5025,3775 5025,3609.04 5385,3249.04 v1(5385,3215)
"HP STOP LATCH": J4.28 U30.15 | length 971.9
  L1-TOP w10: v1(8215,3060) U30.15@8215,3191.1
  L3-Signal w10: J4.28@8020,3820 8070,3770 8070,3340 8215,3195 v1(8215,3060)
HP_STOP_BUF_N: U32.53 U45.2 | length 1290.6
  L1-TOP w10: U32.53@9019.21,1953.15 9136.85,1953.15 v1(9240,1850) 9270,1850 9295,1875 9295,1960 9320,1985 9500,1985 9540,1945 9540,1605 9500,1565 v1(9430,1565)
  L6-BOT w10: U45.2@9331.57,1490 9370,1490 9430,1550 v1(9430,1565)
HP_STOP_LATCH: U30.5 U32.87 | length 1077.9
  L1-TOP w10: U30.5@8165,2828.9 8165,2910 v1(8175,2920) ; U32.87@8739.68,2449.21 8739.68,2659.69 v1(8750,2670)
  L4-Signal w10: v1(8175,2920) 8175,2785 8214,2746 8674,2746 v1(8750,2670)
IBD1: R64.2 R107.1 TP30.1 U6.7 U20.6 | length 2090.4
  L1-TOP w10: U6.7@3570,421.57 3591.57,421.57 3620,450 3745,450 3765.12,429.88 ; R64.2@3765.12,380 3765.12,429.88 ; TP30.1@4370,405 TP30.1@4370,390 ; U20.6@5261.57,510 5256.57,515 5220,515 5205,500 5205,459.88 R107.1@5150,404.88 5150,345 5127,322 4443,322 4375,390 TP30.1@4370,390 ; 3765.12,429.88 3769.88,429.88 3795,455 3895,455 3930,420 3930,335 3945,320 4075,320 4120,365 4345,365 TP30.1@4370,390
IBD2: R59.2 R84.1 TP32.1 U6.8 U11.8 | length 2370.5
  L1-TOP w10: U6.8@3570,618.43 3570,655 3590,675 3730,675 3765,710 3765,730 R59.2@3765.12,730 3775.12,720 4135,720 4180,765 ; R84.1@4250,1025 4250,935.12 ; U11.8@4638.43,1090.12 4625,1076.69 4625,955.12 4540,870.12 4315,870.12 4250,935.12 ; TP32.1@4670,390 4670,400 4615,455 4280,455 4220,515 4220,680 4180,720 4180,895 4220.12,935.12 4250,935.12
IBD3: R51.2 R273.1 TP31.1 U6.1 U37.6 | length 2259.1
  L1-TOP w10: R51.2@3165.12,380 3228.43,380 U6.1@3270,421.57 3270,485 3275,485 v1(3300,510)
  L3-Signal w10: TP31.1@4520,390 4520,435 v1(4725,640)
  L6-BOT w10: v1(3300,510) 3365,510 3390,485 3625,485 3790,320 4460,320 4520,380 TP31.1@4520,390 ; v1(4725,640) 4750,665 U37.6@4750,710 ; U37.6@4750,738.43 4750,860 4795.12,905.12 4795.12,990 R273.1@4785.12,1000
IBE: R56.2 R87.1 TP27.1 U7.7 U14.6 | length 2164.8
  L1-TOP w10: U7.7@3516.57,2095 3511.57,2090 3440,2090 3360.12,2010.12 3360.12,1879.88 3470,1770 3815,1770 3860,1815 4240,1815 4265,1840 4265,1945 TP27.1@4170,2040 4330,2200 4425,2200 4485.12,2260.12 R87.1@4485.12,2275 4530,2275 4570,2315 U14.6@4671.57,2315
IBN: R60.2 R281.1 TP25.1 U7.14 U12.6 | length 2308.9
  L1-TOP w10: U7.14@3750,2395 U7.14@3713.43,2395 3778.43,2460 R60.2@3814.88,2460 3814.88,2470.88 3857,2513 3957,2513 4130,2340 TP25.1@4170,2340 ; U12.6@4870,1511.57 4870,1465 4890,1445 4960,1445 v1(4975,1430)
  L6-BOT w10: TP25.1@4170,2340 4170,2320 4415,2075 4415,1865 4445,1835 4535,1835 4555,1855 4595,1855 4625,1825 4760,1825 4770,1835 4830,1835 4960,1705 4960,1554.88 R281.1@5010,1504.88 5010,1465 v1(4975,1430)
IBS: R53.2 R269.1 TP26.1 U7.1 U12.10 | length 2350.5
  L1-TOP w10: U7.1@3516.57,2395 3495,2395 3415,2475 R53.2@3410.12,2475 3465.12,2530 3975,2530 4065,2440 4170,2440 4240,2370 4240,2260 TP26.1@4170,2190 TP26.1@4205,2190 ; v1(4785,1790) 4820,1755 U12.10@4820,1708.43
  L6-BOT w10: TP26.1@4170,2190 4265,2095 4265,2050 4355,1960 4355,1820 4395.12,1779.88 R269.1@4490,1779.88 4490.12,1780 4490.12,1774.88 4530,1735 4645,1735 4700,1790 v1(4785,1790) 4775,1780
IBW: R69.2 R104.1 TP28.1 U7.8 U14.8 | length 2280.6
  L1-TOP w10: U7.8@3713.43,2095 3738.43,2070 3780,2070 3860,1990 R69.2@3860,1970 ; R69.2@3869.88,1965 3869.88,1880.12 3895,1855 4135,1855 TP28.1@4170,1890 TP28.1@4155,1890 ; v1(4030,1760) 4240,1760 4290,1810 4290,2110 4340,2160 4565,2160 4610,2205 4808.43,2205 U14.8@4868.43,2265 4920,2265 4984.88,2200.12 R104.1@5070,2200.12
  L6-BOT w10: v1(4030,1760) 4160,1890 TP28.1@4170,1890
"LAB SELECT LATCH": J4.44 U35.15 | length 1107.9
  L1-TOP w10: v1(9295,3045) U35.15@9295,3181.1
  L3-Signal w10: J4.44@8820,3820 8865,3775 8865,3560 9295,3130 v1(9295,3045)
LAB_SELECT_LATCH: U32.65 U35.5 | length 924.9
  L1-TOP w10: U32.65@9019.21,2189.37 9184.37,2189.37 9195,2200 v1(9240,2200) 9340,2300 9340,2649.04 9245,2744.04 U35.5@9245,2818.9
LOCAL_CPLD_CLOCK: R169.2 U28.11 U29.3 U32.22 | length 1505.6
  L1-TOP w10: U29.3@8042.32,2395.04 8090.04,2395.04 8110,2415 8145,2415 8165,2435 ; R169.2@8044.88,2570 8105,2509.88 8140.12,2509.88 8165,2485 8165,2390 8170,2385 8170,1950 v1(8200,1920) 8325,1920 8377.83,1972.83 U32.22@8420.79,1972.83 ; U28.11@8158.43,1640 8205,1640 v1(8260,1695)
  L6-BOT w10: v1(8200,1920) 8225,1920 8260,1885 v1(8260,1695)
"MTR CNTR ERR": J3.19 R73.1 | length 702.2
  L1-TOP w10: v1(3990,3210) 3990,3140.12 R73.1@4015,3115.12
  L3-Signal w10: J3.19@3780,3720 3780,3565 3990,3355 v1(3990,3210)
"MTR CNTR ERR LATCH": J4.29 U30.14 | length 751.2
  L1-TOP w10: v1(8265,3110) U30.14@8265,3191.1
  L3-Signal w10: J4.29@8120,3720 8120,3340 8265,3195 v1(8265,3110)
MTR_CNTR_ERR_BUF: U19.2 U32.36 | length 4880.2
  L1-TOP w10: v1(5175,1950) U19.2@5251.57,1950 ; v1(8650,1630) 8650,1745 8680.63,1775.63 U32.36@8680.63,1850.79
  L3-Signal w10: v1(5175,1950) 5185,1950 5245,1890 5245,1600 5345,1500 6150.96,1500 6280.96,1630 6455,1630 6475,1610 6895,1610 7057,1772 7188,1772 7300,1660 7360,1660 7406,1614 7406,1384 7545,1245 7710,1245 7938,1473 8088,1473 8153,1538 8522,1538 8555,1505 8630,1505 8660,1535 8660,1620 v1(8650,1630)
MTR_CNTR_ERR_LATCH: U30.6 U32.86 | length 1078.1
  L1-TOP w10: U30.6@8215,2828.9 8215,2900 v1(8235,2920) ; U32.86@8759.37,2449.21 8759.37,2529.37 8785,2555 v1(8785,2670)
  L6-BOT w10: v1(8235,2920) 8235,2760 8300,2695 8760,2695 v1(8785,2670)
NetC4_2: C4.2 D5.A D18.K R15.2 R207.2 U2.2 | length 2090
  L1-TOP w10: C4.2@1361.89,753.11 C4.2@1389.53,753.11 ; C4.2@1384.88,780 1384.88,819.88 1405,840 1705,840 v1(1730,865) ; R15.2@1494.76,1208.11 1554.65,1208.11 1582.32,1235.79 D5.A@1662.32,1235.79 ; v1(1595,1325) 1595,1295.43 D5.A@1654.65,1235.79 ; v1@1734.65,874.65 1734.65,883.11 1879.65,883.11 1904.65,858.11 U2.2@1904.65,784.69
  L6-BOT w10: R207.2@1384.88,760 1384.88,789.88 1415,820 1680,820 1725,865 v1(1730,865) ; D18.K@1654.65,1235.79 1595,1295.43 v1(1595,1325) 1675,1325 1720,1280 1720,875 v1(1730,865) ; 1744.65,879.65 v1(1730,865)
NetC5_2: C5.2 R7.2 R208.2 U1.12 | length 784.1
  L1-TOP w10: U1.12@1118.43,550 1180,550 1250,480 R7.2@1274.88,480 1275,480.12 1275,530 1285,540 1420,540 1435.12,555.12 C5.2@1435.12,600 C5.2@1415.12,580 ; R7.2@1304.88,480 R7.2@1304.88,489.88 ; C5.2@1435.12,569.88 1495,510 v1(1495,515)
  L6-BOT w10: R208.2@1324.88,600 1384.88,540 1470,540 v1(1495,515)
NetC6_2: C6.2 D4.K D16.A R10.2 R204.2 U3.3 | length 1262.1
  L1-TOP w10: R10.2@1475.12,2450 1475.12,2419.88 1500,2395 1645,2395 1705.12,2455.12 C6.2@1740,2455.12 ; C6.2@1734.65,2468.23 C6.2@1739.76,2463.11 ; v1(1825,2485) 1769.88,2485 C6.2@1740,2455.12 ; U3.3@2186.22,2598.11 2129.65,2598.11 2109.65,2618.11 2026.89,2618.11 1995,2650 1814.21,2650 D4.K@1734.65,2570.43 1734.65,2460.47 C6.2@1740,2455.12
  L6-BOT w10: D16.A@1734.65,2570.43 1739.76,2565.32 R204.2@1739.76,2463.11 1803.11,2463.11 v1(1825,2485)
NetC7_2: C7.2 D2.K D17.A R12.2 R205.1 U4.3 | length 1523.5
  L1-TOP w10: R12.2@1505.12,1980 1505.12,1944.88 1540,1910 1645,1910 v1(1665,1890) C7.2@1729.76,1954.76 ; C7.2@1729.76,1973.11 1729.76,1812.99 1779.65,1763.11 2024.65,1763.11 2094.65,1833.11 U4.3@2166.22,1833.11 ; D2.K@1812.68,2120 1857.68,2165 v1(1880,2165)
  L6-BOT w10: v1(1665,1890) 1695,1890 1729.76,1924.76 1729.76,2055.32 D17.A@1704.65,2080.43 1840.43,2080.43 1880,2120 v1(1880,2165)
NetC8_2: C8.2 R25.1 R212.2 | length 374.3
  L1-TOP w10: C8.2@1759.76,643.11 C8.2@1729.76,673.11 ; v1(1774.65,758.11) 1729.76,713.23 C8.2@1729.76,673.11 ; R25.1@1844.88,650 1800,650 1776.89,673.11 C8.2@1729.76,673.11
  L6-BOT w10: R212.2@1729.76,673.11 1729.76,713.23 v1(1774.65,758.11)
NetC9_2: C9.2 D2.A D17.K R11.2 R26.2 U4.2 | length 1124.4
  L1-TOP w10: R11.2@1475.12,2180 1580,2180 D2.A@1643.66,2116.34 ; v1(1705,2180) 1647.32,2122.32 1647.32,2047.68 1660,2035 1765,2035 1784.65,2015.35 1784.65,1887.99 C9.2@1844.65,1827.99 R26.2@1964.65,1827.99 1964.76,1828.11 2024.65,1828.11 2079.65,1883.11 U4.2@2166.22,1883.11
  L6-BOT w10: D17.K@1704.65,2245.79 1705,2245.43 v1(1705,2180)
NetC11_2: C11.2 D4.A D16.K R9.2 R219.2 U3.2 | length 1250.5
  L1-TOP w10: R9.2@1590,2444.88 1634.88,2444.88 1655,2465 1655,2590 1734.65,2669.65 1764.65,2669.65 1767.99,2672.99 C11.2@2074.65,2672.99 2099.53,2648.11 U3.2@2186.22,2648.11 ; D4.A@1734.65,2735.79 1734.65,2700.35 v1(1765,2670)
  L6-BOT w10: D16.K@1734.65,2735.79 1734.65,2700.35 1800.12,2634.88 R219.2@2070,2634.88
NetC13_2: C13.2 R34.1 R218.2 | length 613
  L1-TOP w10: v1(2385,2995) 2375,2995 2299.76,2919.76 C13.2@2299.76,2868.11 R34.1@2409.53,2868.11
  L6-BOT w10: R218.2@2125.12,2870 2125.12,2910.12 2145,2930 2320,2930 v1(2385,2995)
NetC14_1: C14.1 C70.1 R31.1 R37.2 R44.1 U4.9 | length 1123.5
  L1-TOP w10: v1(2299.65,1258.11) 2299.53,1258.23 2299.53,1523.11 R31.1@2289.53,1533.11 2289.53,1667.99 2304.65,1683.11 2444.65,1683.11 2474.65,1713.11 2529.53,1713.11 R37.2@2534.65,1718.23 2584.53,1718.23 2654.65,1648.11 R44.1@2654.65,1637.99
  L6-BOT w10: C70.1@2289.53,1527.99 C70.1@2289.53,1533.11 2299.65,1522.99 v1(2299.65,1258.11)
NetC14_2: C14.2 C70.2 R31.2 R48.1 U4.8 | length 2355.2
  L1-TOP w10: U4.8@2363.07,1633.11 2399.76,1596.42 R31.2@2399.76,1533.11 2409.76,1523.11 2409.76,1272.99 v1(2419.65,1263.11) ; C14.2@2414.76,1348.11 2458.11,1348.11 2485,1375 2485,1420 2530,1465 2716.54,1465 2756.54,1505 2885,1505 2965,1585 2965,1650 2934.65,1680.35 2934.65,2228.11 3119.76,2413.23 R48.1@3119.76,2463.11
  L6-BOT w10: C70.2@2399.76,1533.11 2469.65,1463.23 2469.65,1313.11 v1(2419.65,1263.11)
NetC17_1: C17.1 R41.1 R228.2 R230.1 R232.1 SW1.10 U4.13 | length 2060.1
  L1-TOP w10: U4.13@2363.07,1883.11 2419.65,1883.11 C17.1@2444.53,1907.99 ; C17.1@2474.65,1907.99 R41.1@2594.65,1907.99 2594.65,1868.11 2634.65,1828.11 2724.65,1828.11 2830.28,1933.74 SW1.10@2860,1933.74
  L6-BOT w10: R232.1@2529.53,2213.11 2459.53,2213.11 R228.2@2414.65,2168.23 2268.23,2168.23 2225,2125 2225,1880 2250,1855 2485,1855 2515,1885 2635.96,1885 2684.7,1933.74 SW1.10@2860,1933.74 ; R230.1@2659.76,1793.11 2679.65,1793.11 2820.28,1933.74
NetC17_2: C17.2 D7.K D25.A U4.14 | length 808.9
  L1-TOP w10: v1(2264.65,1918.11) 2279.65,1933.11 U4.14@2363.07,1933.11 2363.07,1936.54 2444.76,2018.23 C17.2@2474.65,2018.23 2501.97,2045.55 D7.K@2501.97,2253.11
  L6-BOT w10: v1(2264.65,1918.11) 2286.97,1940.43 D25.A@2564.65,1940.43
NetC18_1: C18.1 C72.1 R233.1 R236.2 R240.1 U2.9 | length 1551.1
  L1-TOP w10: U2.9@2104.65,1011.54 2104.65,1048.11 2159.65,1103.11 2464.65,1103.11 2539.53,1177.99 2539.53,1359.53 v1(2545,1365)
  L6-BOT w10: R233.1@2539.53,1303.11 2539.53,1359.53 v1(2545,1365) 2544.88,1365.12 C72.1@2544.88,1430 2565,1450.12 2565,1560 2583,1578 2677,1578 2760,1495 2895,1495 2925.12,1525.12 R236.2@2925.12,1570 R240.1@3034.88,1570
NetC18_2: C18.2 C72.2 R66.1 R233.2 U2.8 | length 2948.9
  L1-TOP w10: U2.8@2154.65,1011.54 2154.65,1028.11 2199.65,1073.11 2549.65,1073.11 2564.65,1088.11 2564.65,1118.11 2649.76,1203.23 C18.2@2649.76,1303.11 2650,1303.35 v1(2650,1365) ; v1(3705,1515) 3750,1560 R66.1@3804.88,1560
  L6-BOT w10: R233.2@2649.76,1298.59 2593.08,1241.92 2500,1241.92 2488.46,1253.46 2488.46,1468.46 2525,1505 2525,1560 2560,1595 2695,1595 2778,1512 2852,1512 2865,1525 2865,1595 2895,1625 3525,1625 3555,1595 3555,1535 3610,1480 3640,1480 3675,1515 v1(3705,1515) ; R233.2@2649.76,1303.11 2649.76,1364.76 2655.12,1370.12 C72.2@2655.12,1430
NetC20_1: C20.1 R245.2 | length 159.8
  L1-TOP w10: C20.1@3428.54,1565 v1(3508.43,1565)
  L6-BOT w10: R245.2@3428.54,1565 v1(3508.43,1565)
NetC20_2: C20.2 R238.1 SW2.2 | length 1428.6
  L1-TOP w10: v1(3125,1270) 3225,1370 3225,1490 3300,1565 C20.2@3318.31,1565
  L6-BOT w10: SW2.2@2860,1055 2932.76,1055 2959.65,1028.11 2959.65,948.11 3039.76,867.99 R238.1@3039.76,794.65 ; R238.1@3045.12,800 R238.1@3035.12,790 3080,790 3200,910 3200,975 3070,1105 3070,1215 v1(3125,1270)
NetC21_1: C21.1 R52.1 R238.2 R242.1 R256.2 SW2.1 U8.6 | length 2284.8
  L1-TOP w10: R52.1@3300,1205.12 C21.1@3430,1205.12 3449.88,1205.12 v1(3520,1135) ; 3430,1165.12 3435,1170.12 ; v1@3523.43,1135 3553.43,1105 U8.6@3605,1105
  L6-BOT w10: SW2.1@2860,976.26 2860,917.76 2929.53,848.23 2929.53,794.65 R238.2@2924.88,790 2924.88,750.12 2940,735 3070,735 3090,755 3090,775 3235,920 3235,990 3195,1030 3195,1230 3225,1260 3355,1260 3390.12,1224.88 R242.1@3390.12,1205 3450,1205 v1(3520,1135) ; R242.1@3420,1205 3595,1380 3770,1380 3790,1360 R256.2@3790,1265.12
NetC21_2: C21.2 D9.K D27.A U8.7 | length 481.8
  L1-TOP w10: C21.2@3430,1094.88 3490.12,1094.88 3530,1055 U8.7@3605,1055 U8.7@3600.12,1059.88 ; D9.K@3482.68,890 3482.68,1017.68 v1(3525,1060)
  L6-BOT w10: D27.A@3462.68,990 3462.68,997.68 v1(3525,1060)
NetC22_2: C22.2 D3.A D15.K R13.2 R57.1 U8.2 | length 4888.4
  L1-TOP w10: v1(1570,1755) 1517.87,1755 R13.2@1469.76,1803.11 1469.76,1705.24 1519.21,1655.79 D3.A@1629.65,1655.79 1629.65,1645.35 v1(1685,1590) ; v1(3115,1160) 3165,1160 3313.43,1308.43 R57.1@3313.43,1339.88 3503.54,1339.88 3538.43,1305 U8.2@3605,1305
  L3-Signal w10: v1(1685,1590) 1685,1465 1650,1430 1650,1275 1600,1225 1600,745 1760,585 2080,585 2100,565 2825,565 2955,695 2955,1210 2985,1240 2985,1405 3080,1500 3160,1500 3185,1475 3185,1230 v1(3115,1160)
  L6-BOT w10: v1(1570,1755) 1570,1715 1629.21,1655.79 D15.K@1629.65,1655.79
NetC25_2: C25.2 R117.1 R123.1 U19.5 | length 825.2
  L1-TOP w10: v1(5155,1750) 5160,1750 5210,1800 5285,1800 5370,1715 5370,1695 5400,1665 5455,1665 5485,1635 5485,1600.12 R117.1@5520,1565.12 C25.2@5710,1565.12 R123.1@5830,1565.12
NetC26_2: C26.2 R127.1 R132.1 U40.1 | length 935.5
  L1-TOP w10: C26.2@6130,1274.88 R132.1@6250,1274.88 6250,1204.88 R127.1@6205.12,1160 6215,1160 v1(6285,1090) ; R132.1@6245,1289.88 R132.1@6250,1294.88
  L3-Signal w10: v1(6285,1090) 6310,1090 6355,1045 6355,840 6460,735 v1(6510,735)
  L6-BOT w10: U40.1@6488.43,670 6488.43,713.43 v1(6510,735)
NetC27_2: C27.2 R125.1 R129.1 U42.1 | length 1212.1
  L1-TOP w10: R125.1@6145.12,1740 6170.12,1765 6260.12,1765 C27.2@6370,1874.88 6320,1924.88 6320,1925 6290,1955 6290,2160 6210,2240 R129.1@6210,2284.88 6339.88,2284.88 6360,2305 v1(6360,2310)
  L6-BOT w10: v1(6360,2310) 6590,2310 6618.43,2281.57 U42.1@6618.43,2260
